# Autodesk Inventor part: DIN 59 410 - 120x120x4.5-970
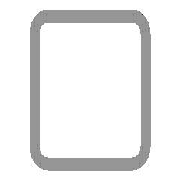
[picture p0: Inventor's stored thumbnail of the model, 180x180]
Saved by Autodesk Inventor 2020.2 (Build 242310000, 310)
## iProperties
Manager: www.cadconsulting.pl
Company: Fabian Stasiak CAD Consulting
Created: 2015-02
Part Number: DIN 59 410 - 120x120x4.5-970
Material: Stal, miękka
Description: Rurki stalowe o przekroju kwadratowym formowane na gorąco
Document SubType Name: Modellieren
Standard: DIN
Designer: F.Stasiak
Standards Organization: DIN
Language: pl-PL
Size Designation: 120x120x4.5
Categories: <MemberInstance><Categories><Category DisplayName="Kształtowniki konstrukcyjne" InternalName="089c4875-fa83-4c05-b084-43b9cc11f5ed" Mnemonic="GRDR"><CategoryPar
Stock Number: 120x120x4.5
Density: 7.85 g/cm^3
Appearance: Częściowo polerowany
Catalog Web Link: www.expertbooks.pl
IsCustomPart: 1
G_L: 970,000 mm
G_W: 120,000 mm
G_H: 120,000 mm
+2FD35156-07EB-433B-8BAA-9E0404799C17+CUTDETAIL1: Wytnij
+0DF8B167-686C-451D-BA79-14E046739711+CUTDETAIL2: Wytnij
_CCFamilyMember: 200
_CCFamilyDisplayName: DIN 59410 (Kwadrat) - Rurki stalowe o przekroju kwadratowym formowane na gorąco — Standard DIN 59410 (Kwadrat) został wycofany i zastąpiony przez standard DIN E
_FrameMemberDoc: Frame Member File
_Version: 15.0.0
_GetPNFromCC: 1
Author: F.Stasiak
Subject: Zbiór ćwiczeń. Autodesk Inventor 2020. Kurs Professional
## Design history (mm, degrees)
node "Płaszczyzna początkowa"
node "Płaszczyzna końcowa"
sketch "Szkic"
  geometry: L1 (-51, 60)-(51, 60); L2 (60, 51)-(60, -51); L3 (51, -60)-(-51, -60); L4 (-60, -51)-(-60, 51); L5 (-86.61, 0)-(86.61, 0) reference; L6 (0, -86.61)-(0, 86.61) reference; L7 (-51, 55.5)-(51, 55.5); L8 (55.5, 51)-(55.5, -51); L9 (51, -55.5)-(-51, -55.5); L10 (-55.5, -51)-(-55.5, 51); A1 r 9 centre (-51, 51) between (-51, 60) and (-60, 51); A2 r 9 centre (51, 51) between (60, 51) and (51, 60); A3 r 9 centre (51, -51) between (51, -60) and (60, -51); A4 r 9 centre (-51, -51) between (-60, -51) and (-51, -60); A5 r 4.5 centre (-51, 51) between (-51, 55.5) and (-55.5, 51); A6 r 4.5 centre (51, 51) between (55.5, 51) and (51, 55.5); A7 r 4.5 centre (51, -51) between (51, -55.5) and (55.5, -51); A8 r 4.5 centre (-51, -51) between (-55.5, -51) and (-51, -55.5); 3 further points
  constraints: 16 end point, 16 point on circle, 8 centre point, 8 tangent, 6 point on line, 4 parallel, 3 equal radius, 3 perpendicular, 1 horizontal, 7 other
  dimensions: "b" = 120 distance of point (-60, 60) point (60, 60); "msp_r" = 9 radius of A1 (= 2 x ParT); "d8" = 60 distance between parallel lines of L4 L6 (= d9); "d9" = 60 distance between parallel lines of L3 L5 (= 0.5 x b); "d10" = 4.5 distance between parallel lines of L3 L9 (= ParT)
extrude "Bryła" new body sketch "Szkic" taper "d4" = 0 deg; stored distance "NLG" = 10
node "Driven Length"
  sketch "Sketch2"
    geometry: L1 (0, 0)-(10, 0) reference
    constraints: 2 end point, 1 horizontal
  workplane "Work Plane3"
  sketch "Sketch3"
    geometry: L1 (-2, 60)-(12, 60) reference; L2 (-2, 1030)-(12, 1030) reference
    dimensions: "d14" = 970 distance between parallel lines of L1 L2 (derived)
node "Płaszczyzna konstrukcyjna4"
feature "Podział1"
node "Płaszczyzna konstrukcyjna5"
feature "Podział2"
body "Solid1"
other parameters: "ParT" = 4.5, "G_L" = 970 (= d14) [user parameter], "d13" = 90 deg
